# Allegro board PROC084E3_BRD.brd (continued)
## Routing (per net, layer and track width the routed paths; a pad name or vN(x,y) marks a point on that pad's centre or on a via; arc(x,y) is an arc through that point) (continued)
MCAN4_TX: length 94
  L03_SIG1 w0.102: v1(71.19,100.5) 67.51,100.5 49.1,118.91 48.78,118.91 43.67,124.02 43.67,155.88 39.39,160.16 J15.1
  BOTTOM w0.173: U29.54 70.69,100 v1(71.19,100.5) ; U15.1 29.46,160.92 J15.1
MCAN5_RX: length 98.3
  L03_SIG1 w0.102: v1(71.19,97) 71.19,97.58 70.74,98.04 70.74,98.69 71.09,99.04 71.38,99.04 71.65,99.31 71.65,100.69 71.38,100.96 67.75,100.96 49.52,119.18 49.52,120.09 45.23,124.38 45.23,156.54 37.92,163.84 J13.2
  BOTTOM w0.173: U29.47 70.69,96.5 v1(71.19,97) ; R126.1 29.08,162.7 J13.2
MCAN5_TX: length 100.5
  L03_SIG1 w0.102: J13.1 36.97,166.38 45.54,157.82 45.54,124.55 68.9,101.18 71.48,101.18 71.88,100.78 71.88,99.18 v1(71.19,98.5)
  BOTTOM w0.173: U29.50 70.69,98 v1(71.19,98.5) ; J13.1 29.59,167.02 U11.1
MCAN6_RX: length 105.6
  L03_SIG1 w0.102: J11.2 36.58,170.07 46.02,160.62 46.02,124.39 68.99,101.41 71.57,101.41 72.11,100.88 72.11,97.27 71.3,96.46 71,96.46 70.74,96.19 70.74,95.46 v1(71.19,95)
  BOTTOM w0.173: J11.2 28.96,168.8 R117.1 ; v1(71.19,95) 70.69,94.5 U29.43
MCAN6_TX: length 111.5
  L03_SIG1 w0.102: J11.1 39.96,172.61 46.33,166.24 46.33,124.4 69.09,101.64 71.8,101.64 72.42,101.03 72.42,97.22 v1(71.19,96)
  BOTTOM w0.173: U9.1 29.72,173.12 J11.1 ; U29.45 70.69,95.5 v1(71.19,96)
MCAN7_RX: length 118.4
  L03_SIG1 w0.102: J9.2 31.34,177.15 41.2,177.15 46.79,171.57 46.79,124.33 69.22,101.9 71.9,101.9 72.64,101.16 72.64,95.8 71.33,94.48 71.02,94.48 70.74,94.19 70.74,93.46 v1(71.19,93)
  BOTTOM w0.173: v1(71.19,93) 70.69,92.5 U29.39 ; R113.1 29.21,175.02 J9.2
MCAN7_TX: length 120
  L03_SIG1 w0.102: J9.1 31.34,177.46 41.33,177.46 47.09,171.69 47.09,124.35 69.31,102.13 72.03,102.13 72.87,101.28 72.87,95.68 v1(71.19,94)
  BOTTOM w0.173: U8.1 29.59,179.21 J9.1 ; U29.41 70.22,93.5 70.72,94 v1(71.19,94)
MCAN9_RX: length 117.1
  TOP w0.173: J1.55 v1(84.01,106.01)
  L03_SIG1 w0.102: J7.2 42.24,182.01 48.54,175.71 48.54,165.84 62.26,152.13 62.26,137.85 76.78,123.33 76.78,114.93 75.16,113.31 75.16,107.43 76.36,106.24 81.94,106.24 82.19,106.49 83.52,106.49 v1(84.01,106.01)
  BOTTOM w0.173: J7.2 29.46,181.24 R110.1
MCAN9_TX: length 124.8
  TOP w0.173: v1(82.86,106.01) 83.31,106.01 83.81,105.51 J1.53
  L03_SIG1 w0.102: v1(82.86,106.01) 76.27,106.01 74.87,107.4 74.87,113.34 76.55,115.02 76.55,123.24 62.03,137.76 62.03,152.03 48.23,165.83 48.23,175.58 43.33,180.48 29.57,180.48 28.93,181.12 28.93,183.25 J7.1
  BOTTOM w0.173: U7.1 29.46,185.31 J7.1
MCAN11_RX: length 123.5
  TOP w0.173: J1.60 v1(92.43,107.01)
  L03_SIG1 w0.102: v1(92.43,107.01) 88.61,110.83 81.09,110.83 80.36,111.57 80.36,112.78 77.02,116.13 77.02,123.79 64.59,136.21 64.59,158.13 49.43,173.29 49.43,177.92 37.87,189.47 31.34,189.47 J4.2
  BOTTOM w0.173: J4.2 29.21,187.34 R107.1
MCAN11_TX: length 128.8
  TOP w0.173: v1(93.58,107.01) 93.08,106.51 J1.58
  L03_SIG1 w0.102: J4.1 31.34,189.78 38,189.78 49.73,178.04 49.73,173.31 64.82,158.22 64.82,138.24 77.24,125.82 77.24,116.25 80.7,112.79 80.7,111.57 81.17,111.1 89.49,111.1 v1(93.58,107.01)
  BOTTOM w0.173: U6.1 29.72,191.4 J4.1
MCAN/PWM_SEL: length 76.7
  TOP w0.173: v1(81.35,90.36) 81.02,90.36 80.93,90.44 75.79,90.44 75.04,91.19 75.04,99.1 77.5,101.56 79.06,101.56 79.34,101.28 v1(79.34,101.26) ; J2.32 v1(93.58,50.63)
  BOTTOM w0.173: v1(81.35,90.36) 81.22,90.22 81.22,75.26 80.06,74.11 80.06,66.14 81.29,64.91 82.29,64.91 83.67,63.54 91.83,63.54 92.23,63.14 92.54,63.14 93.83,61.85 93.83,58.99 94.82,57.99 94.82,51.88 v1(93.58,50.63) ; v1(79.34,101.26) 79,101.26 78.14,102.13 R167.2
MCAN/PWM_SEL_R: length 2.4
  BOTTOM w0.173: R164.1 R167.1 76.78,101.59 76.77,101.59 U29.1
MCU_ADC1_AIN0: length 183
  L06_SIG2 w0.102: J24.51 26.19,23.2 26.19,39.18 26.78,39.77 26.78,94.15 31.47,98.84 31.47,108.81 32.41,109.75 32.41,112.98 34.58,115.15 34.58,121.61 34.29,121.89 34.29,122.69 34.82,123.22 34.82,134.18 37.03,136.39 47.54,136.39 47.56,136.41 47.59,136.41 51.32,140.14 68.24,140.14 69.75,141.65 69.75,144.13 J16.6
  BOTTOM w0.173: J16.6 71.05,147.34 72.34,148.63 77.6,148.63 80.88,151.91 U17.3
MCU_ADC1_AIN1: length 186.8
  L06_SIG2 w0.102: J24.53 31.91,17.08 25.96,23.03 25.96,39.28 26.55,39.87 26.55,95.69 31.24,100.39 31.24,122.2 34.01,124.96 34.01,133.98 36.65,136.62 47.44,136.62 51.26,140.44 66.59,140.44 67.41,141.26 67.41,144.33 J16.8
  BOTTOM w0.173: J16.8 68.51,147.08 70.93,149.49 74.35,149.49 78.16,153.31 U12.3
MCU_ADC1_AIN2: length 176.2
  L06_SIG2 w0.102: J16.10 64.72,144.18 64.72,141.44 64.13,140.85 51.29,140.85 47.29,136.85 36.55,136.85 33.59,133.89 33.59,125.35 31.01,122.77 31.01,100.48 26.32,95.79 26.32,40 25.73,39.41 25.73,22.93 29.91,18.75 J24.55
  BOTTOM w0.173: J16.10 65.97,147.75 68.48,150.26 72.97,150.26 74.63,151.91 U18.3
MCU_ADC1_AIN3: length 183.2
  L06_SIG2 w0.102: J24.57 27.91,20.37 25.5,22.77 25.5,39.62 26.08,40.21 26.08,95.87 30.78,100.58 30.78,123.41 32.76,125.38 32.76,136.32 34.03,137.59 38.23,137.59 38.73,137.09 47.03,137.09 51.18,141.24 52.94,141.24 52.94,141.24 61.47,141.24 62.15,141.92 62.15,144.15 J16.12
  BOTTOM w0.173: J16.12 63.43,149.15 65.46,151.17 70.97,151.17 71.76,151.96 U13.3
MCU_ADC1_AIN4: length 178.8
  TOP w0.173: v1(62.79,149.83) 62.34,149.38 R280.2
  L06_SIG2 w0.102: v1(62.79,149.83) 60.29,147.33 53.45,147.33 43.49,137.37 39.06,137.37 38.52,137.91 33.89,137.91 31.45,135.47 31.45,125.49 30.56,124.59 30.56,100.67 25.85,95.97 25.85,40.55 24.21,38.9 24.21,12.96 25.06,12.11 28.54,12.11 J24.56
  BOTTOM w0.173: v1(62.79,149.83) 62.79,151.04 63.66,151.91 67.67,151.91 67.92,152.17 U19.3
MCU_ADC1_AIN5: length 180.9
  TOP w0.173: R278.2 v1(59.07,149.65)
  L06_SIG2 w0.102: v1(59.07,149.65) 57.13,147.71 52.35,147.71 42.25,137.61 39.28,137.61 38.62,138.26 33.75,138.26 31.22,135.74 31.22,125.93 30.33,125.04 30.33,101.82 25.63,97.12 25.63,40.65 23.98,39 23.98,12.86 24.96,11.88 30.31,11.88 J24.54
  BOTTOM w0.173: U14.3 63.66,155.54 59.07,150.96 v1(59.07,149.65)
MCU_ADC1_AIN6: length 173.3
  TOP w0.173: R274.2 v1(55.81,149.65)
  L06_SIG2 w0.102: v1(55.81,149.65) 55.32,149.16 53.12,149.16 42.04,138.09 41.09,138.09 40.62,138.56 33.63,138.56 29.97,134.91 29.97,101.79 25.4,97.21 25.4,40.74 23.75,39.09 23.75,12.77 24.89,11.62 32.05,11.62 J24.52
  BOTTOM w0.173: U20.3 57.21,151.91 55.81,150.52 v1(55.81,149.65)
MCU_ADC1_AIN7: length 192.5
  L06_SIG2 w0.102: v1(74.56,139.67) 61.25,139.67 60.76,139.18 50.72,139.18 47.58,136.04 39.46,136.04 38.73,135.31 36.97,135.31 35.32,133.66 35.32,115.01 32.83,112.52 32.83,99.87 30.96,98 27.05,94.09 27.05,63.2 28.03,62.21 28.03,59.73 27.05,58.75 27.05,39.7 26.46,39.11 26.46,23.34 32.36,17.44 33.95,17.44 J24.49
  BOTTOM w0.173: v1(74.56,139.67) R148.1 77.02,140.45 77.95,141.38 77.95,148.26 79.95,150.27 85.23,150.27 87.05,152.09 U16.3
MCU_ADC_EXT_TRIGGER1: length 100.7
  TOP w0.173: J2.103 v1(84.01,73.63)
  L03_SIG1 w0.102: v1(84.01,73.63) 82.66,73.63 80.64,71.62 80.64,67.94 79.98,67.28 68.53,67.28 63.89,62.64 63.89,44.76 63.04,43.91 61.72,43.91 58.83,41.01 58.83,39.88 52.54,33.6 41.68,33.6 37.21,29.13 37.21,28.63 36.35,27.77 35.17,27.77 26.91,19.51 26.91,14.48 J24.58
MDIO0_MDC: length 149.9
  TOP w0.173: v1(58.35,58.45) 58.95,57.85 73.55,57.85 v1(74.92,59.22) ; J1.97 83.77,121.51 83.42,121.17 v1(80.32,121.17)
  L03_SIG1 w0.102: v1(58.35,58.45) 57.91,58.01 57.91,41.99 54.81,38.89 54.81,38.74 54.32,38.24 52.93,38.24 52.53,38.64 52.53,39.12 52.26,39.38 51.88,39.38 51.38,38.89 51.38,38.74 51.12,38.47 49.78,38.47 46.73,35.41 40.66,35.41 36,30.75 v1(36,29.06)
  BOTTOM w0.173: v1(36,29.06) 36.08,29.06 36.39,28.75 U40.20 ; U35.10 59,59.1 v1(58.35,58.45) ; v1(80.32,121.17) 80.32,115.12 78.67,113.47 78.67,110.42 81.15,107.93 81.17,107.93 81.34,107.76 81.34,106.2 80.36,105.23 80.36,98.54 79.74,97.91 79.74,75.6 79.03,74.89 79.03,67.82 78.49,67.28 78,67.28 76.62,65.9 71.03,65.9 69.21,64.08 69.21,60.32 70.31,59.22 U34.10 v1(74.92,59.22)
MDIO0_MDIO: length 146.4
  TOP w0.173: v1(80.57,122.02) 81.08,121.51 83.06,121.51 83.56,122.01 J1.99 ; v1(58.35,61.05) 59.52,62.22 v1(69.71,62.22)
  L03_SIG1 w0.102: v1(58.35,61.05) 57.51,60.2 57.51,52.72 56.87,52.08 56.87,50.38 57.51,49.75 57.51,41.94 55.43,39.87 54.65,39.87 53.9,39.12 53.9,38.97 53.4,38.47 53.02,38.47 52.76,38.74 52.76,39.21 52.35,39.61 51.79,39.61 51.68,39.51 49.12,39.51 45.25,35.64 40.45,35.64 36.17,31.36 35.2,31.36 v1(34.37,30.52)
  BOTTOM w0.173: v1(80.57,122.02) 80.85,121.74 80.85,115.17 79.05,113.37 79.05,110.52 81.3,108.28 81.31,108.28 81.68,107.9 81.68,107.89 81.73,107.84 81.73,105.62 80.74,104.64 80.74,98.09 80.08,97.44 80.08,75.41 79.37,74.7 79.37,67.68 78.63,66.94 78.15,66.94 76.77,65.56 76.74,65.56 76.6,65.41 71.35,65.41 69.71,63.77 v1(69.71,62.22) 69.71,61.78 70.31,61.17 U34.13 ; U40.19 35.89,28.46 34.37,29.99 v1(34.37,30.52) ; U35.13 v1(58.35,61.05)
MDIO_MDC_SEL0: length 24.6
  TOP w0.173: J2.34 92.57,51.13 v1(92.58,51.12)
  BOTTOM w0.173: v1(92.58,51.12) 93.42,51.12 94.48,52.18 94.48,57.84 93.37,58.95 93.37,61.8 93.36,61.82 93.36,61.82 92.79,62.39 92.79,62.39 92.56,62.61 84.7,62.61 84.17,63.13 R219.1
MDIO_MDC_SEL1: length 40.8
  TOP w0.173: v1(82.28,62.04) 82.03,61.79 80.54,61.79 76.88,65.45 68.76,65.45 v1(68,64.69) ; J2.36 92.77,51.63 v1(93.13,52)
  BOTTOM w0.173: v1(93.13,52) 93.75,52 94.1,52.34 94.1,56.26 93.01,57.35 93.01,61.68 92.65,62.04 v1(82.28,62.04) ; R298.1 v1(68,64.69)
MDIO_MDC_SEL_PRG0: length 2.8
  BOTTOM w0.173: U34.1 R215.1 82.07,63.12 R219.2
MDIO_MDC_SEL_PRG1: length 2.8
  BOTTOM w0.173: U35.1 R298.2 R299.1
MUX_MAIN_UART4_RTSN: length 100.6
  TOP w0.173: U42.3 70.97,42.44 v1(71.65,43.12)
  L06_SIG2 w0.102: v1(56.03,91.79) 56.03,90.82 55.27,90.06 55.27,79.97 53.9,78.6 53.9,73.45 52.25,71.8 52.25,68.06 54.13,66.18 v1(54.58,66.18)
  BOTTOM w0.173: v1(71.65,43.12) 70.61,43.12 66.55,47.18 66.55,49.26 59.51,56.31 58.62,56.31 54.58,60.34 v1(54.58,66.18) ; U22.3 46.34,118.72 45.54,117.92 45.54,109.42 46.56,108.4 54.87,108.4 56.57,106.7 56.57,92.9 56.03,92.37 v1(56.03,91.79)
MUX_MAIN_UART4_RXD: length 99.3
  TOP w0.173: U42.6 v1(72.92,43.07)
  L06_SIG2 w0.102: v1(55.65,66.18) 55.04,66.79 53.87,66.79 52.55,68.11 52.55,71.64 54.33,73.42 54.33,78.58 55.65,79.9 55.65,89.37 v1(56.92,90.64)
  BOTTOM w0.173: v1(72.92,43.07) 72.26,43.73 70.56,43.73 66.95,47.34 66.95,49.42 59.67,56.7 58.78,56.7 55.65,59.83 v1(55.65,66.18) ; U22.6 46.47,116.77 45.9,116.19 45.9,109.57 46.71,108.75 55.02,108.75 56.92,106.85 v1(56.92,90.64)
MUX_MAIN_UART4_TXD: length 101.6
  TOP w0.173: v1(72.92,44.21) 73.57,44.86 U42.10
  L06_SIG2 w0.102: v1(55.17,90.67) 54.89,90.39 54.89,80.02 53.57,78.7 53.57,73.65 51.92,72 51.92,67.07 53.26,65.72 56.39,65.72 v1(56.85,66.18)
  BOTTOM w0.173: U22.10 44.02,116.12 45.19,114.95 45.19,109.27 46.42,108.04 54.72,108.04 56.21,106.55 56.21,93.28 55.17,92.24 v1(55.17,90.67) ; v1(56.85,66.18) 56.44,65.78 56.44,59.63 58.95,57.11 59.84,57.11 67.36,49.6 67.36,47.51 70.66,44.21 v1(72.92,44.21)
MUX_MC/BP_SEL: length 211.4
  TOP w0.173: v1(97.71,109.84) 98.27,110.4 98.27,134.49 96.67,136.08 67.31,136.08 65.98,137.41 R273.2 ; U44.1 90.48,20.13 v1(91.44,21.1) ; J2.20 v1(90.22,47.63)
  L06_SIG2 w0.102: v1(91.44,21.1) 91.87,21.1 93.95,23.18 93.95,32.55 97.59,36.18 97.59,71.69 99.69,73.8 99.69,107.63 97.71,109.62 v1(97.71,109.84)
  BOTTOM w0.173: v1(91.44,21.1) 91.85,21.5 91.85,35.73 90.65,36.92 90.65,47.2 v1(90.22,47.63)
MUX_PRG1_UART0_RTSN: length 17.9
  TOP w0.173: v1(48.96,119.37) 49.52,118.81 50.6,118.81 51.13,119.34 v1(64.01,119.34)
  BOTTOM w0.173: U22.2 v1(48.96,119.37) ; U23.2 v1(64.01,119.34)
MUX_PRG1_UART0_RXD: length 20.5
  TOP w0.173: v1(49.98,116.77) 62.58,116.77 63.09,117.29 64.48,117.29 v1(65.02,116.74)
  BOTTOM w0.173: v1(65.02,116.74) 64.37,117.39 U23.5 ; U22.5 49.33,117.42 v1(49.98,116.77)
MUX_PRG1_UART0_TXD: length 20.5
  TOP w0.173: v1(54.98,117.39) 43.01,117.39 42.44,116.83 40.52,116.83 v1(39.94,117.42)
  BOTTOM w0.173: v1(39.94,117.42) 40.59,116.77 U22.11 ; v1(54.98,117.39) 55.63,116.74 U23.11
PERIPH_RSTZ: length 163.5
  TOP w0.173: v1(96.11,50.13) 93.07,50.13 92.57,49.63 J2.28
  L03_SIG1 w0.102: v1(96.11,50.13) 98.65,52.67 98.65,100.78 97.21,102.22 97.21,121.48 86.44,132.25 86.44,158.03 67.31,177.15 67.31,187.27 J5.10
  BOTTOM w0.173: v1(96.11,50.13) 93.07,50.13 92,49.06 TP28.1
PG_V2V5: length 13.2
  TOP w0.254: v1(62.64,100.55) 62.18,100.09 R7.2 52.22,100.17 v1(52.22,100.9)
  BOTTOM w0.254: U28.3 52.45,100.67 v1(52.22,100.9) ; v1(62.64,100.55) 62.26,100.55 61.96,100.25 U27.5
PRG0_MDC: length 47.5
  TOP w0.173: U5.16 v1(37.62,53.96)
  L03_SIG1 w0.102: v1(53.24,49.32) 52.61,48.68 39.5,48.68 37.85,50.34 37.85,53.74 v1(37.62,53.96)
  L06_SIG2 w0.102: v1(69.33,59.13) 64.28,59.13 56.96,51.81 56.96,50.63 56.34,50 53.93,50 v1(53.24,49.32)
  BOTTOM w0.173: U37.16 v1(53.24,49.32) ; v1(69.33,59.13) 69.88,58.57 U34.9
PRG0_MDIO: length 48.3
  TOP w0.173: v1(38.51,53.96) 38.51,53.99 38.51,53.99 38.51,54.04 38.12,54.43 U5.17
  L03_SIG1 w0.102: v1(54.13,49.32) 53.67,49.77 38.73,49.77 38.07,50.43 38.07,53.69 38.35,53.96 v1(38.51,53.96)
  L06_SIG2 w0.102: v1(54.13,49.32) 56.7,49.32 57.88,50.5 57.88,50.91 64.96,57.99 69.33,57.99 69.81,58.48 69.81,60.52 v1(69.82,60.52)
  BOTTOM w0.173: U37.17 53.74,48.86 54.13,49.24 54.13,49.29 54.13,49.3 v1(54.13,49.32) ; U34.12 v1(69.82,60.52)
PRG0_MDIO0_MDC: length 6.8
  L03_SIG1 w0.102: v1(75.49,60.3) 75.49,60.48 v1(77.27,62.27)
  BOTTOM w0.173: U34.11 75.06,59.87 v1(75.49,60.3) ; v1(77.27,62.27) 77.47,62.47 U34.2
PRG0_MDIO0_MDIO: length 8.6
  TOP w0.173: v1(80.52,60.61) 80.38,60.47 R287.1
  BOTTOM w0.173: U34.14 76.3,61.82 77.6,60.52 U34.5 80.43,60.52 v1(80.52,60.61)
PRG0_RGMII1_100MBPS: length 13.7
  TOP w0.173: J21.A13 6.78,50.43 4.97,48.62 4.97,44.27 7.13,42.11 R80.2 7.13,40.93 Q9.3
PRG0_RGMII1_1000MBPS: length 10
  TOP w0.173: J21.A14 14.24,43.16 R82.2 14.24,40.93 Q11.3
PRG0_RGMII1_ACT_LED: length 5.9
  TOP w0.173: J21.A11 10.41,55.9 Q7.3
PRG0_RGMII1_CLK_OUT: length 7.7
  TOP w0.173: v1(54.24,47.5) 51.44,50.31 v1(50.95,50.31)
  BOTTOM w0.173: U37.18 v1(54.24,47.5) ; TP16.1 v1(50.95,50.31)
PRG0_RGMII1_D0_N: length 41.6
  BOTTOM w0.102: J21.A2 13.82,49.27 13.82,48.33 14.15,47.99 14.15,46.69 15.87,44.98 25.25,44.98 27.75,42.47 50.22,42.47 50.34,42.59 U37.2
PRG0_RGMII1_D0_P: length 41.6
  BOTTOM w0.102: J21.A1 13.62,48.15 13.88,47.88 13.88,46.58 15.76,44.71 25.14,44.71 27.64,42.21 50.22,42.21 50.34,42.09 U37.1
PRG0_RGMII1_D1_N: length 38.1
  BOTTOM w0.102: U37.5 50.34,44.09 50.22,43.97 27.65,43.97 25.93,45.69 18.07,45.69 16.69,47.08 16.69,48.02 16.41,48.3 16.41,49.32 J21.A4
PRG0_RGMII1_D1_P: length 38.2
  BOTTOM w0.102: J21.A3 16.18,48.15 16.42,47.91 16.42,46.97 17.96,45.43 25.82,45.43 27.54,43.71 50.22,43.71 50.34,43.59 U37.4
PRG0_RGMII1_D2_N: length 35.6
  BOTTOM w0.102: U37.8 50.34,45.59 50.22,45.47 43.04,45.47 42.29,44.72 28.19,44.72 26.46,46.45 19.84,46.45 19.23,47.06 19.23,48.02 18.95,48.3 18.95,49.32 J21.A6
PRG0_RGMII1_D2_P: length 35.7
  BOTTOM w0.102: U37.7 50.34,45.09 50.22,45.21 43.16,45.21 42.4,44.45 28.08,44.45 26.35,46.18 19.73,46.18 18.96,46.95 18.96,47.91 18.72,48.15 J21.A5
PRG0_RGMII1_D3_N: length 32.8
  BOTTOM w0.102: U37.11 50.34,47.09 50.22,46.97 42.64,46.97 41.27,45.61 29.21,45.61 27.74,47.08 22,47.08 21.77,47.31 21.77,47.99 21.49,48.27 21.49,49.32 J21.A8
PRG0_RGMII1_D3_P: length 32.8
  BOTTOM w0.102: J21.A7 21.24,48.15 21.5,47.88 21.5,47.2 21.89,46.81 27.63,46.81 29.1,45.34 41.39,45.34 42.75,46.71 50.22,46.71 50.34,46.59 U37.10
PRG0_RGMII1_GPIO0_100: length 63.1
  TOP w0.173: Q9.1 v1(5.91,37.45) ; v1(55.5,38.93) R92.1
  L03_SIG1 w0.102: v1(5.91,37.45) 6.37,36.99 18.8,36.99 26.34,29.45 29.83,29.45 30.94,28.34 36.27,28.34 36.75,28.82 36.75,29.32 42.38,34.96 51.53,34.96 v1(55.5,38.93)
  BOTTOM w0.173: R92.1 v1(55.5,38.93) 56.24,39.67 U37.39
PRG0_RGMII1_GPIO1: length 4.7
  TOP w0.173: v1(54.36,38.93) R91.1
  BOTTOM w0.173: R91.1 v1(54.36,38.93) 54.74,38.93 55.9,40.09 55.9,40.69 55.74,40.84 U37.40
PRG0_RGMII1_LED0: length 4.4
  TOP w0.173: v1(50.93,38.93) R88.1
  BOTTOM w0.173: R88.1 v1(50.93,38.93) 52.24,40.24 U37.47
PRG0_RGMII1_LED1_1000: length 54.1
  TOP w0.173: v1(52.07,38.93) R89.1 ; Q11.1 v1(13.02,37.45)
  L03_SIG1 w0.102: v1(52.07,38.93) 52.07,38.29 48.96,35.18 40.76,35.18 36.53,30.95 36.53,28.94 36.15,28.56 31.04,28.56 29.86,29.74 26.89,29.74 18.57,38.06 13.64,38.06 v1(13.02,37.45)
  BOTTOM w0.173: U37.46 52.74,39.6 v1(52.07,38.93) R89.1
PRG0_RGMII1_LED2_ACT: length 57.4
  TOP w0.173: Q7.1 v1(11.36,61.21) ; v1(53.21,38.93) R90.1
  L03_SIG1 w0.102: v1(11.36,61.21) 14.29,58.28 20.74,58.28 40.45,38.58 47.43,38.58 49.28,40.43 51.86,40.43 53.21,39.08 v1(53.21,38.93)
  BOTTOM w0.173: R90.1 v1(53.21,38.93) 53.21,41.31 U37.45
PRG0_RGMII1_RBIAS: length 2.3
  TOP w0.173: v1(49.91,47.59) 50.43,47.59 50.52,47.49 R77.2
  BOTTOM w0.173: U37.12 v1(49.91,47.59)
PRG0_RGMII1_RD0: length 107.2
  TOP w0.173: v1(82.54,113.59) 82.56,113.59 82.58,113.56 82.83,113.56 83.77,114.51 J1.69
  L06_SIG2 w0.102: v1(82.54,113.59) 82.6,113.65 82.6,114.52 82.14,114.97 82.14,116.58 82.54,116.97 88.53,116.97 88.93,116.56 88.93,89.14 87.35,87.56 87.35,73 85.97,71.61 85.97,70.06 84.48,68.58 83.78,68.58 83.56,68.8 81.41,68.8 79.75,67.15 77.77,67.15 72.3,61.67 72.3,58.67 68.65,55.02 65.27,55.02 61.37,51.12 61.37,45.13 63.73,42.76 v1(63.73,41.57)
  BOTTOM w0.173: R241.1 64.27,41.69 64.15,41.57 v1(63.73,41.57)
PRG0_RGMII1_RD0_R: length 7.1
  BOTTOM w0.173: R241.2 62.89,42.72 61.27,42.72 R78.1 60.59,42.1 R79.2 60.56,43.43 58.65,43.43 58.49,43.59 U37.33
PRG0_RGMII1_RD1: length 107.7
  TOP w0.173: J1.77 84.26,116.51 84.01,116.26 v1(83.88,116.26)
  L06_SIG2 w0.102: v1(83.88,116.26) 84.13,116.51 86.54,116.51 87.43,115.62 87.43,105.76 88.08,105.1 88.08,100.83 87.5,100.26 87.5,92.43 88.47,91.46 88.47,89.33 84.79,85.64 84.79,77.38 85.75,76.42 85.75,72.13 85.22,71.59 83.32,71.59 80.24,68.52 78.09,68.52 71.75,62.17 71.75,58.85 68.4,55.5 65.07,55.5 60.88,51.32 60.88,43.8 59.11,42.02 59.11,39.81 59.95,38.96 61.48,38.96 62.25,39.74 64.17,39.74 64.78,40.35 v1(64.78,41.24)
  BOTTOM w0.173: R242.1 64.55,41.24 v1(64.78,41.24)
PRG0_RGMII1_RD1_R: length 6.4
  BOTTOM w0.173: R242.2 62.62,41.33 60.27,41.33 59.91,41.69 59.91,42.28 59.09,43.09 U37.34
PRG0_RGMII1_RD2: length 107.9
  TOP w0.173: J1.75 v1(86.28,116.01)
  L06_SIG2 w0.102: v1(62.92,38.57) 62.54,38.57 62.5,38.62 62.18,38.62 62.18,38.62 62.02,38.62 61.65,38.25 59.61,38.25 59.12,37.76 57.88,37.76 57.28,38.36 57.28,40.69 60.66,44.07 60.66,51.41 64.97,55.73 68.3,55.73 71.51,58.94 71.51,62.26 78,68.75 80.15,68.75 81.99,70.59 81.99,81.89 82.09,81.99 82.37,81.99 82.47,81.89 82.47,80.43 82.58,80.33 82.85,80.33 82.96,80.43 82.96,84.13 88.25,89.42 88.25,91.37 87.27,92.34 87.27,100.35 87.85,100.93 87.85,104.98 87.57,105.26 87.2,105.63 87.2,115.1 v1(86.28,116.01)
  BOTTOM w0.173: R243.1 64.1,39.27 63.41,38.57 v1(62.92,38.57)
PRG0_RGMII1_RD2_R: length 8.2
  BOTTOM w0.173: R243.2 62.82,39.94 61.28,39.94 R85.1 R84.2 59.89,40.7 59.48,41.1 59.48,41.98 58.87,42.59 U37.35
PRG0_RGMII1_RD3: length 107.3
  TOP w0.173: v1(83.14,116.24) 83.17,116.24 83.68,116.75 83.99,116.75 84.25,117.01 J1.79
  L06_SIG2 w0.102: v1(62.31,38.16) 62.15,38.16 61.86,37.87 59.6,37.87 58.36,36.62 57.49,36.62 56.9,37.21 56.9,40.75 60.43,44.28 60.43,51.51 64.88,55.96 68.21,55.96 71.27,59.02 71.27,62.84 78.24,69.81 78.94,69.81 81.46,72.33 81.46,82.96 81.99,83.49 88.02,89.52 88.02,91.27 87.02,92.27 87.02,100.42 87.62,101.02 87.62,104.88 86.97,105.53 86.97,114.53 85.89,115.61 83.88,115.61 83.25,116.24 v1(83.14,116.24)
  BOTTOM w0.173: R244.1 v1(62.31,38.16)
PRG0_RGMII1_RD3_R: length 5.6
  BOTTOM w0.173: U37.36 58.56,42.09 58.91,41.74 58.91,39.57 60.32,38.16 R244.2
PRG0_RGMII1_REF_CLK: length 34.4
  L06_SIG2 w0.102: v1(54.23,52.12) 54.62,52.12 59.72,57.22 61.19,57.22 74.63,70.65 v1(78.53,70.65)
  BOTTOM w0.173: v1(54.23,52.12) 54.23,50.61 R232.1 ; R196.2 v1(78.53,70.65)
PRG0_RGMII1_REF_CLK_R: length 1.9
  BOTTOM w0.173: R196.1 76.83,70.62 U31.2
PRG0_RGMII1_RESET#: length 20.2
  TOP w0.173: v1(47.74,34.5) 54.88,34.5 57.89,37.51 57.89,38.93 57.39,39.42 54.06,39.42 v1(53.74,39.74)
  BOTTOM w0.173: U37.43 54.24,40.24 v1(53.74,39.74) ; U38.4 v1(47.74,34.5)
PRG0_RGMII1_RX_CTL: length 107.2
  TOP w0.173: J1.71 v1(84.01,115.01)
  L06_SIG2 w0.102: v1(84.01,115.01) 85.03,115.01 85.34,114.7 85.34,109.64 86.74,108.24 86.74,105.44 87.39,104.79 87.39,101.12 86.79,100.52 86.79,92.18 87.79,91.18 87.79,89.61 81.9,83.72 81.23,83.05 81.23,72.49 78.78,70.04 74.39,70.04 70.42,66.07 70.42,58.49 68.11,56.19 64.78,56.19 60.2,51.6 60.2,44.48 56.51,40.8 56.51,39.12 55.13,37.73 55.13,35.06 55.66,34.53 56.3,34.53 56.81,35.04 v1(56.81,35.74)
  BOTTOM w0.173: v1(56.81,35.74) 57.22,35.33 58.46,35.33 58.65,35.51 R250.1
PRG0_RGMII1_RX_CTL_R: length 7.7
  BOTTOM w0.173: R250.2 57.3,36.34 57.3,37.56 R251.2 R93.1 58.04,38.9 56.74,40.21 U37.38
PRG0_RGMII1_RXC: length 107.5
  TOP w0.173: v1(82.97,114.8) 82.97,115.12 83.36,115.51 J1.73
  L06_SIG2 w0.102: v1(64.57,43.59) 64.57,41.76 63.87,41.06 63.36,41.06 62.67,41.75 62.67,42.12 61.11,43.68 61.11,51.22 65.16,55.28 68.59,55.28 72.01,58.7 72.01,62.11 77.4,67.5 79.56,67.5 82.73,70.68 84.71,70.68 86.06,72.02 86.06,76.79 85.09,77.75 85.09,85.62 88.7,89.23 88.7,91.56 88.57,91.69 87.73,92.53 87.73,100.17 88.31,100.74 88.31,105.21 87.66,105.86 87.66,115.72 86.64,116.74 82.97,116.74 82.41,116.17 82.41,115.36 v1(82.97,114.8)
  BOTTOM w0.173: R240.1 64.27,43.89 v1(64.57,43.59)
PRG0_RGMII1_RXC_R: length 5.1
  BOTTOM w0.173: R240.2 62.73,44 59.24,44 59.11,43.87 58.7,43.87 58.48,44.09 U37.32
PRG0_RGMII1_TD0: length 101
  TOP w0.173: J1.72 v1(92.43,115.01)
  L06_SIG2 w0.102: v1(92.43,115.01) 92.43,114.86 92.78,114.52 93.74,114.52 94.06,114.21 94.06,111.87 90.66,108.47 90.66,88.68 89.41,87.43 89.41,75.83 88.64,75.07 88.64,71.59 87.47,70.42 87.47,67.95 85.49,65.97 81.03,65.97 78.02,62.96 75.38,62.96 73.52,61.1 73.52,55.2 65.09,46.76 64.92,46.76 64.73,46.95 64.73,47.09 68.43,50.79 68.43,51.03 68.33,51.13 68.09,51.13 64.98,48.02 v1(62.36,48.02)
  BOTTOM w0.173: R235.1 v1(62.36,48.02)
PRG0_RGMII1_TD0_R: length 3.7
  BOTTOM w0.173: R235.2 60.02,47.44 60.02,46.95 59.16,46.09 U37.28
PRG0_RGMII1_TD1: length 100.9
  TOP w0.173: J1.70 93.08,114.51 v1(93.58,114.01)
  L06_SIG2 w0.102: v1(62.36,49.16) 64.57,49.16 72.23,56.82 72.47,56.82 72.57,56.72 72.57,56.48 68.1,52.02 68.1,51.88 68.43,51.56 68.57,51.56 73.29,56.28 73.29,61.2 75.33,63.24 77.94,63.24 80.9,66.19 85.39,66.19 87.16,67.96 87.16,70.45 88.35,71.64 88.35,75.34 89.15,76.15 89.15,87.49 89.18,87.52 89.18,87.52 89.69,88.03 89.69,107.91 93.58,111.8 v1(93.58,114.01)
  BOTTOM w0.173: R234.1 v1(62.36,49.16)
PRG0_RGMII1_TD1_R: length 4.3
  BOTTOM w0.173: R234.2 59.67,48.24 59.67,47.14 59.12,46.59 U37.27
PRG0_RGMII1_TD2: length 101
  TOP w0.173: J1.78 93.08,116.51 v1(93.58,116.01)
  L06_SIG2 w0.102: v1(93.58,116.01) 93.58,115.58 93.47,115.48 92.2,115.48 91.77,115.06 91.77,113.91 93.33,112.35 93.33,111.94 89.41,108.02 89.41,88.31 88.93,87.82 88.93,80.1 88.82,80 88.05,80 87.95,79.9 87.95,79.62 88.05,79.52 88.82,79.52 88.93,79.41 88.93,79.13 88.82,79.03 88.05,79.03 87.95,78.93 87.95,78.65 88.05,78.55 88.82,78.55 88.93,78.45 88.93,78.17 88.82,78.07 88.05,78.07 87.95,77.97 87.95,77.69 88.05,77.58 88.82,77.58 88.93,77.48 88.93,76.35 88.77,76.19 88.06,76.19 87.96,76.09 87.96,71.83 86.81,70.69 86.81,68.13 86.48,67.8 86.1,67.8 85.84,68.06 84.59,68.06 84.42,67.9 84.42,67.43 84.59,67.27 85.71,67.27 85.82,67.16 85.82,66.94 85.3,66.42 82.48,66.42 82.38,66.53 82.38,67.79 82.2,67.98 81.69,67.98 77.18,63.46 74.76,63.46 73.06,61.77 73.06,58.07 65.3,50.31 v1(62.36,50.31)
  BOTTOM w0.173: R233.1 v1(62.36,50.31)
PRG0_RGMII1_TD2_R: length 4.9
  BOTTOM w0.173: U37.26 58.94,47.09 59.33,47.48 59.33,49.04 R233.2
PRG0_RGMII1_TD3: length 100.9
  TOP w0.173: J1.76 v1(92.43,116.01)
  L06_SIG2 w0.102: v1(62.36,51.45) 65.96,51.45 72.84,58.32 72.84,61.88 74.64,63.69 77.07,63.69 81.93,68.55 83.49,68.55 83.68,68.35 84.2,68.35 84.26,68.29 85.68,68.29 86.27,68.88 86.27,71.59 87.71,73.03 87.71,87.41 87.82,87.52 88.06,87.52 88.2,87.38 88.2,80.61 88.34,80.47 88.54,80.47 88.67,80.6 88.67,88.08 89.18,88.58 89.18,108.14 92.94,111.9 92.94,112.38 91.55,113.78 91.55,115.82 91.74,116.01 v1(92.43,116.01)
  BOTTOM w0.173: R229.1 v1(62.36,51.45)
PRG0_RGMII1_TD3_R: length 5.3
  BOTTOM w0.173: U37.25 58.57,47.59 58.98,48 58.98,49.84 R229.2
PRG0_RGMII1_TX_CTL: length 101.3
  TOP w0.173: v1(93.58,115.01) 93.08,115.51 J1.74
  L06_SIG2 w0.102: v1(59.77,37.24) 61.02,37.24 61.09,37.17 62.18,37.17 65.24,40.23 65.24,41.43 65.07,41.6 65.07,45.71 64.96,45.82 64.96,46.12 74.04,55.21 74.04,61.28 75.49,62.73 78.35,62.73 81.36,65.74 85.58,65.74 88.69,68.85 88.69,71.32 88.87,71.5 88.87,74.91 89.64,75.68 89.64,87.33 90.88,88.58 90.88,108.38 94.28,111.78 94.28,114.3 v1(93.58,115.01)
  BOTTOM w0.173: R249.1 v1(59.77,37.24)
PRG0_RGMII1_TX_CTL_R: length 3.9
  BOTTOM w0.173: U37.37 57.24,40.5 59.19,38.56 R249.2
PRG0_RGMII1_TXC: length 101
  TOP w0.173: J1.80 v1(92.43,117.01)
  L06_SIG2 w0.102: v1(92.43,117.01) 93.76,117.01 94.54,116.23 94.54,111.71 91.11,108.28 91.11,88.49 89.92,87.29 89.92,76.53 90.65,75.79 90.65,68.8 87.36,65.51 82.06,65.51 77.39,60.84 75.23,60.84 74.35,59.95 74.35,48.49 71.59,45.73 69.99,45.73 68.35,44.09 66.35,44.09 65.48,44.96 v1(65.48,45.94)
  BOTTOM w0.173: v1(65.48,45.94) 64.54,46.88 R236.1
PRG0_RGMII1_TXC_R: length 3.1
  BOTTOM w0.173: R236.2 59.38,45.66 58.06,45.66 U37.29
PRG0_RGMII1_XIN: length 2.3
  BOTTOM w0.173: R232.2 52.74,50.11 U37.15
PRG0_RGMII1_XOUT: length 2.2
  BOTTOM w0.173: R231.2 52.24,50.15 U37.14
PRG0_RGMII2_100MBPS: length 17.3
  TOP w0.132: 8.46,49.41 9.88,49.41 10.85,50.39 J21.B13
  TOP w0.173: 8.46,49.41 6.78,49.41 5.51,48.15 5.51,44.82 7.21,43.12 9.8,43.12 10.14,42.78 R81.2 10.41,41.78 Q10.3
PRG0_RGMII2_1000MBPS: length 11.2
  TOP w0.173: J21.B14 15.67,43.58 16.89,43.58 17.25,43.21 R83.2 17.25,40.93 Q12.3
PRG0_RGMII2_ACT_LED: length 6.6
  TOP w0.173: Q8.3 13.97,59.65 11.58,57.27 11.58,55.22 J21.B11
PRG0_RGMII2_CLK_OUT: length 7.8
  TOP w0.173: U5.18 v1(38.62,55.78)
  BOTTOM w0.173: v1(38.62,55.78) 35.82,52.97 TP15.1
PRG0_RGMII2_D0_N: length 26.1
  TOP w0.102: U5.2 34.72,60.69 34.6,60.81 30.82,60.81 29.59,59.58 26.91,59.58 24.98,57.65 15.47,57.65 14.15,56.33 14.15,54.88 13.87,54.6 13.87,53.58 J21.B2
PRG0_RGMII2_D0_P: length 26.2
  TOP w0.102: J21.B1 13.64,54.75 13.88,54.99 13.88,56.44 15.36,57.91 24.87,57.91 26.8,59.84 29.48,59.84 30.71,61.07 34.6,61.07 34.72,61.19 U5.1
PRG0_RGMII2_D1_N: length 22.8
  TOP w0.102: J21.B4 16.41,53.58 16.41,54.6 16.69,54.88 16.69,56.07 17.69,57.08 25.61,57.08 27.23,58.69 33.4,58.69 34.02,59.31 34.6,59.31 34.72,59.19 U5.5
PRG0_RGMII2_D1_P: length 22.9
  TOP w0.102: J21.B3 16.18,54.75 16.42,54.99 16.42,56.19 17.58,57.34 25.5,57.34 27.12,58.96 33.29,58.96 33.91,59.57 34.6,59.57 34.72,59.69 U5.4
PRG0_RGMII2_D2_N: length 19.4
  TOP w0.102: J21.B6 18.95,53.58 18.95,54.6 19.23,54.88 19.23,55.69 19.99,56.46 26.41,56.46 27.76,57.81 34.6,57.81 34.72,57.69 U5.8
PRG0_RGMII2_D2_P: length 19.5
  TOP w0.102: U5.7 34.72,58.19 34.6,58.07 27.65,58.07 26.3,56.72 19.88,56.72 18.96,55.8 18.96,54.99 18.72,54.75 J21.B5
PRG0_RGMII2_D3_N: length 16.2
  TOP w0.102: U5.11 34.72,56.19 34.6,56.31 27.66,56.31 27.22,55.87 22.07,55.87 21.77,55.57 21.77,54.88 21.49,54.6 21.49,53.58 J21.B8
PRG0_RGMII2_D3_P: length 16.3
  TOP w0.102: U5.10 34.72,56.69 34.6,56.58 27.55,56.58 27.11,56.13 21.96,56.13 21.5,55.68 21.5,54.99 21.26,54.75 J21.B7
PRG0_RGMII2_GPIO0_100: length 67.7
  TOP w0.173: v1(29.36,33.21) 25.07,33.21 22.35,35.93 16.56,35.93 15.57,36.92 9.64,36.92 9.46,37.09 Q10.1 ; R56.2 v1(39.88,64.35) 40.62,63.61 U5.39
  L06_SIG2 w0.102: v1(39.88,64.35) 40.34,63.9 40.34,62.4 39.52,61.58 34.21,61.58 33.71,61.08 33.71,49.16 34.32,48.55 34.32,35.91 32.2,33.8 29.95,33.8 v1(29.36,33.21)
  BOTTOM w0.173: v1(39.88,64.35) R56.2
PRG0_RGMII2_GPIO1: length 4.7
  TOP w0.173: R55.2 v1(38.73,64.35) 39.12,64.35 40.28,63.19 40.28,62.61 40.12,62.45 U5.40
  BOTTOM w0.173: v1(38.73,64.35) R55.2
PRG0_RGMII2_LED0: length 4.4
  TOP w0.173: U5.47 36.62,63.04 v1(35.31,64.35) R52.2
  BOTTOM w0.173: v1(35.31,64.35) R52.2
PRG0_RGMII2_LED1_1000: length 54.6
  TOP w0.173: U5.46 37.12,63.68 v1(36.45,64.35) R53.2 ; v1(29.36,34.23) 25.73,34.23 23.22,36.74 17.07,36.74 16.58,37.24 Q12.1
  L06_SIG2 w0.102: v1(36.45,64.35) 36.45,64.15 33.45,61.15 33.45,49.09 34.09,48.46 34.09,36.01 32.31,34.23 v1(29.36,34.23)
  BOTTOM w0.173: v1(36.45,64.35) R53.2
PRG0_RGMII2_LED2_ACT: length 28.8
  TOP w0.173: Q8.1 v1(14.92,61.21) ; U5.45 37.62,62.5 37.47,62.65 37.47,64.23 v1(37.59,64.35) R54.2
  L03_SIG1 w0.102: v1(14.92,61.21) 15.2,61.49 33.94,61.49 35.13,62.68 35.92,62.68 v1(37.59,64.35)
  BOTTOM w0.173: v1(37.59,64.35) R54.2
PRG0_RGMII2_RBIAS: length 2.3
  TOP w0.173: U5.12 v1(34.29,55.69)
  BOTTOM w0.173: v1(34.29,55.69) 34.81,55.69 34.9,55.79 R227.2
PRG0_RGMII2_RD0: length 65
  TOP w0.173: v1(48.63,61.23) 48.38,60.98 R67.1 ; J1.13 83.36,95.51 v1(82.86,95.01)
  L03_SIG1 w0.102: v1(82.86,95.01) 81.81,93.95 81.81,89.6 75.33,83.12 64.23,83.12 60.59,79.48 60.4,79.48 56.43,79.48 54.56,77.61 54.56,76.6 45.65,67.69 45.65,63.95 46.05,63.55 46.05,63.31 46.08,63.29 46.08,61.12 46.22,60.97 46.81,60.97 47.33,60.45 48.03,60.45 48.63,61.05 v1(48.63,61.23)
PRG0_RGMII2_RD0_R: length 6.8
  TOP w0.173: R67.2 46.91,61 46.34,61.57 45.56,61.57 R223.2 R224.1 44.96,60.96 44.96,60.9 43.81,59.76 42.44,59.76 U5.33
PRG0_RGMII2_RD1: length 65.2
  TOP w0.173: v1(49.23,63.3) 48.33,62.4 R64.1 ; J1.15 v1(84.01,96.01)
  L03_SIG1 w0.102: v1(49.23,63.3) 49.69,63.76 49.69,67.21 57.23,74.74 59.33,74.74 64.06,79.47 73.27,79.47 85.53,91.72 88.89,91.72 89.21,92.05 89.21,95.21 88.41,96.01 v1(84.01,96.01)
PRG0_RGMII2_RD1_R: length 7.2
  TOP w0.173: R64.2 47.35,62.51 47.12,62.74 44.59,62.74 44.26,62.4 44.26,61.11 43.34,60.19 U5.34
PRG0_RGMII2_RD2: length 65
  TOP w0.173: v1(49.05,64.42) 48.74,64.11 48.74,63.91 48.31,63.48 R61.1 ; v1(82.86,96.01) 83.36,96.51 J1.17
  L03_SIG1 w0.102: v1(82.86,96.01) 82.95,96.09 83.27,96.09 83.81,95.55 87.31,95.55 87.71,95.15 87.71,92.28 87.52,92.09 85.56,92.09 73.16,79.69 63.96,79.69 59.24,74.97 55.91,74.97 48.44,67.5 48.44,64.73 48.75,64.42 v1(49.05,64.42)
PRG0_RGMII2_RD2_R: length 9.4
  TOP w0.173: R61.2 47.33,63.97 46.99,64.31 45.49,64.31 R218.1 44.9,63.73 44.91,63.72 R222.2 44.09,63.55 43.91,63.37 43.91,61.73 42.87,60.69 U5.35
PRG0_RGMII2_RD3: length 65
  TOP w0.173: v1(47.16,65.37) 46.49,66.04 R60.1 ; v1(82.86,94.01) 83.36,94.51 J1.9
  L03_SIG1 w0.102: v1(82.86,94.01) 82.12,93.26 82.12,89.59 75.37,82.84 71.37,82.84 71.26,82.74 71.26,82.27 71.16,82.17 70.88,82.17 70.78,82.27 70.78,82.74 70.68,82.84 70.4,82.84 70.3,82.74 70.3,82.27 70.2,82.17 69.92,82.17 69.82,82.27 69.82,82.74 69.71,82.84 69.43,82.84 69.33,82.74 69.33,82.27 69.23,82.17 68.95,82.17 68.85,82.27 68.85,82.74 68.75,82.84 65.94,82.84 65.84,82.74 65.84,82.46 65.94,82.36 67.78,82.36 67.88,82.27 67.88,81.99 67.77,81.88 63.31,81.88 60.68,79.25 56.52,79.25 54.89,77.62 54.89,75.22 51.64,71.97 50.26,71.97 47.16,68.87 v1(47.16,65.37)
PRG0_RGMII2_RD3_R: length 6.3
  TOP w0.173: R60.2 44.5,66.04 44.32,65.87 44.32,64.67 43.51,63.86 43.51,62.02 42.69,61.19 U5.36
PRG0_RGMII2_REF_CLK: length 52.4
  TOP w0.173: R73.1 38.61,52.67 v1(38.61,51.16)
  L03_SIG1 w0.102: v1(38.61,51.16) 38.95,51.16 39.85,50.26 48.87,50.26 55.75,57.14 55.75,60.23 63.15,67.63 65.41,67.63 65.41,67.63 65.79,67.63 67.69,67.63 69.42,69.36 v1(78.53,69.36)
  BOTTOM w0.173: R198.2 v1(78.53,69.36)
PRG0_RGMII2_REF_CLK_R: length 1.9
  BOTTOM w0.173: U31.3 76.86,69.35 R198.1
PRG0_RGMII2_RESET#: length 13.5
  TOP w0.173: U5.43 38.62,62.52 38.55,62.6 38.55,63.12 v1(38.12,63.54) ; U4.4 v1(28.31,65.48)
  BOTTOM w0.173: v1(38.12,63.54) 34.72,63.54 32.78,65.48 v1(28.31,65.48)
PRG0_RGMII2_RX_CTL: length 65.3
  TOP w0.173: v1(42.16,67.58) 41.53,68.21 41.13,68.21 R58.1 ; J1.11 v1(84.01,95.01)
  L03_SIG1 w0.102: v1(42.16,67.58) 41.1,68.64 41.1,75.12 45.95,79.97 53.88,79.97 54.15,79.71 60.49,79.71 64.24,83.45 75.34,83.45 81.31,89.42 81.31,89.75 80.89,90.17 80.89,90.54 81.31,90.96 81.31,94.15 82.63,95.47 83.55,95.47 v1(84.01,95.01)
PRG0_RGMII2_RX_CTL_R: length 7.8
  TOP w0.173: U5.38 41.12,63.64 42.47,65 R209.1 41.04,65.04 R57.2 41.13,65.06 41.68,65.61 41.68,66.58 R58.2
PRG0_RGMII2_RXC: length 65
  TOP w0.173: v1(49.25,62.1) 49.25,60.77 48.03,59.55 46.24,59.55 R68.1 ; J1.7 v1(84.01,94.01)
  L03_SIG1 w0.102: v1(49.25,62.1) 48.27,62.1 47.37,62.99 47.37,64.91 48.18,65.72 48.18,67.6 59.44,78.86 61.11,78.86 63.02,80.76 69.23,80.76 69.33,80.86 69.33,81.14 69.23,81.24 68.2,81.24 68.1,81.35 68.1,81.63 68.2,81.73 74.87,81.73 83.44,90.29 83.44,93.44 v1(84.01,94.01)
PRG0_RGMII2_RXC_R: length 2.9
  TOP w0.173: R68.2 44.55,59.41 43.08,59.41 42.86,59.19 U5.32
PRG0_RGMII2_TD0: length 102.6
  TOP w0.173: J1.85 83.36,118.51 v1(82.86,118.01) ; v1(47.98,54.12) 46.84,55.26 R70.1
  L06_SIG2 w0.102: v1(47.98,54.12) 47.98,53.52 48.08,53.42 48.87,53.42 49.35,53.9 49.35,58.39 51.16,60.2 62.83,60.2 75.21,72.58 78.56,72.58 80.26,74.28 80.26,81.89 80.26,86.25 84.81,90.8 84.81,94.68 84.91,94.78 85.19,94.78 85.29,94.68 85.29,92.9 85.39,92.8 85.67,92.8 85.78,92.9 85.78,107.63 81.18,112.23 81.18,117.15 82.04,118.01 v1(82.86,118.01)
PRG0_RGMII2_TD0_R: length 3.7
  TOP w0.173: R70.2 44.4,55.84 44.4,56.33 43.53,57.19 U5.28
PRG0_RGMII2_TD1: length 102
  TOP w0.173: R71.1 v1(46.74,54.12) ; J1.83 v1(84.01,118.01)
  L06_SIG2 w0.102: v1(84.01,118.01) 83.51,118.51 82.21,118.51 80.95,117.25 80.95,112.08 85.55,107.48 85.55,96.26 85.45,96.15 85.12,96.15 85.01,96.26 85.01,98.11 84.89,98.24 84.63,98.24 84.53,98.14 84.53,90.84 80.04,86.34 80.04,81.8 80.04,74.42 78.53,72.91 75.18,72.91 62.72,60.46 51.09,60.46 49.12,58.49 49.12,57.15 47.4,55.43 47.4,53.55 47.3,53.45 46.66,53.45 46.47,53.64 46.47,53.85 v1(46.74,54.12)
PRG0_RGMII2_TD1_R: length 4.3
  TOP w0.173: U5.27 43.5,56.69 44.05,56.14 44.05,55.04 R71.2
PRG0_RGMII2_TD2: length 102.7
  TOP w0.173: R72.1 v1(46.74,52.97) ; v1(82.86,119.01) 83.36,119.51 J1.89
  L06_SIG2 w0.102: v1(82.86,119.01) 82.39,119.01 80.72,117.34 80.72,111.88 85.32,107.28 85.32,99.43 82.35,96.46 82.35,93.84 82.25,93.74 81.97,93.74 81.86,93.84 81.86,94.58 81.76,94.68 81.48,94.68 81.38,94.58 81.38,90.97 81.81,90.54 81.81,90.17 81.38,89.74 81.38,88.01 79.81,86.44 79.81,81.7 79.81,74.58 78.57,73.34 75.22,73.34 63.07,61.19 59.55,61.19 59.24,61.5 54.53,61.5 53.73,60.71 51.02,60.71 48.9,58.58 48.9,57.25 47.29,55.64 46.34,55.64 46.12,55.42 46.12,52.64 46.22,52.53 46.95,52.53 47.05,52.64 47.05,52.87 46.95,52.97 v1(46.74,52.97)
PRG0_RGMII2_TD2_R: length 4.9
  TOP w0.173: R72.2 43.71,54.24 43.71,55.81 43.32,56.19 U5.26
PRG0_RGMII2_TD3: length 102.1
  TOP w0.173: J1.93 83.36,120.51 v1(82.86,120.01) ; R76.1 v1(46.74,51.83)
  L06_SIG2 w0.102: v1(46.74,51.83) 46.52,51.61 46.05,51.61 45.89,51.77 45.89,55.73 46.03,55.87 47.19,55.87 48.67,57.34 48.67,58.77 50.86,60.95 52.91,60.95 53.69,61.73 59.02,61.73 59.47,62.18 63.69,62.18 75.14,73.62 78.49,73.62 79.58,74.71 79.58,81.61 79.58,86.53 81.15,88.11 81.15,89.91 80.89,90.17 80.89,90.54 81.15,90.8 81.15,95.65 85.09,99.58 85.09,107.13 80.49,111.72 80.49,119.07 81.43,120.01 v1(82.86,120.01)
PRG0_RGMII2_TD3_R: length 5.1
  TOP w0.173: R76.2 43.36,53.44 43.36,54.98 42.65,55.69 U5.25
PRG0_RGMII2_TX_CTL: length 102.4
  TOP w0.173: J1.91 v1(84.01,120.01) ; R59.1 43.64,66.51 43.92,66.79 46.65,66.79 47.88,65.57 v1(47.88,64.4)
  L06_SIG2 w0.102: v1(84.01,120.01) 84.01,120.04 82.18,121.86 82.18,122.18 81.86,122.5 80.37,122.5 79.82,121.96 79.82,120.67 80.04,120.45 80.04,111.4 84.63,106.8 84.63,99.91 83.28,98.55 81.89,98.55 79.6,96.27 79.6,87.57 79.12,87.09 79.12,81.42 79.12,74.9 78.43,74.21 75.07,74.21 63.61,62.74 51.23,62.74 50.09,63.88 48.4,63.88 v1(47.88,64.4)
PRG0_RGMII2_TX_CTL_R: length 4
  TOP w0.173: U5.37 41.62,63.06 43.6,65.04 R59.2
PRG0_RGMII2_TXC: length 102.4
  TOP w0.173: R69.1 v1(46.74,56.4) ; J1.87 v1(84.01,119.01)
  L06_SIG2 w0.102: v1(46.74,56.4) 47.22,56.4 48.44,57.62 48.44,58.87 52.08,62.51 63.7,62.51 75.09,73.9 78.45,73.9 79.35,74.81 79.35,81.51 79.35,86.63 79.91,87.19 79.91,91.4 80.04,91.53 80.29,91.53 80.39,91.43 80.39,89.22 80.49,89.12 80.77,89.12 80.87,89.22 80.87,89.86 80.67,90.07 80.67,90.64 80.87,90.85 80.87,95.82 84.86,99.81 84.86,107.03 80.26,111.63 80.26,119.36 81.37,120.47 83.26,120.47 83.54,120.18 83.54,119.11 83.64,119.01 v1(84.01,119.01)
PRG0_RGMII2_TXC_R: length 3.1
  TOP w0.173: U5.29 42.44,57.62 43.76,57.62 R69.2
PRG0_RGMII2_XIN: length 2.3
  TOP w0.173: R73.2 37.12,53.17 U5.15
PRG0_RGMII2_XOUT: length 2.2
  TOP w0.173: R74.2 36.62,53.13 U5.14
PRG0_RGMII3_REF_CLK_R: length 1.9
  BOTTOM w0.173: U31.4 76.83,68.08 R208.1
PRG0_RGMII4_REF_CLK_R: length 2.1
  BOTTOM w0.173: U31.5 68.13,68.08 R207.1
PRG0_RGMII_INT#: length 75.7
  TOP w0.173: R86.1 52.99,40.33 53.16,40.5 v1(53.74,40.5) 54.48,39.77 58.97,39.77 61.51,37.23 73.51,37.23 82.4,46.12 83.17,46.12 83.67,46.63 J2.15 ; U5.44 38.12,62.72 v1(38.05,62.79)
  L03_SIG1 w0.102: v1(53.74,40.5) 53.74,42.79 51.38,45.15 41,45.15 36.5,49.65 36.5,61.23 v1(38.05,62.79)
  BOTTOM w0.173: U37.44 v1(53.74,40.5)
PRG1_IEP0_EDIO_OUTVALID: length 83.9
  TOP w0.173: J2.26 93.08,49.13 v1(93.58,49.63)
  L03_SIG1 w0.102: v1(93.58,49.63) 93.58,33.82 92.28,32.53 92.28,20.28 90.14,18.15 51.74,18.15 50.65,17.05 47.17,17.05 46.52,17.7 45.07,17.7 43.91,16.54 J24.41
PRG1_MDC: length 59.9
  TOP w0.173: v1(59.37,58.45) 58.85,58.96 58.85,59.94 58.4,60.39 53.24,60.39 52.05,61.58 52.05,65.15 48.84,68.36 48.84,79.21 50.44,80.81 55.66,80.81 v1(56.16,80.3) ; U3.16 v1(37.62,84.7)
  L03_SIG1 w0.102: v1(56.16,80.3) 55.5,80.96 46.33,80.96 43.18,84.11 38.21,84.11 v1(37.62,84.7)
  BOTTOM w0.173: U35.9 v1(59.37,58.45) ; U30.16 v1(56.16,80.3)
PRG1_MDIO: length 61.7
  TOP w0.173: U3.17 38.12,85.16 38.51,84.77 38.51,84.72 38.51,84.72 v1(38.51,84.7) ; v1(57.05,80.3) 56.19,81.17 49.99,81.17 48.5,79.68 48.5,68.2 51.69,65.01 51.69,61.2 53.15,59.75 v1(58.35,59.75)
  L03_SIG1 w0.102: v1(38.51,84.7) 43,84.7 46.33,81.37 55.99,81.37 v1(57.05,80.3)
  BOTTOM w0.173: U35.12 59,60.4 v1(58.35,59.75) ; v1(57.05,80.3) 57.05,80.28 57.05,80.28 57.05,80.23 56.66,79.84 U30.17
PRG1_MDIO0_MDC: length 6.7
  BOTTOM w0.173: U35.2 64.85,62.35 62.25,59.75 U35.11
PRG1_MDIO0_MDIO: length 19.3
  TOP w0.173: R288.1 74.88,61.45 73.36,59.93 68.27,59.93 v1(67.8,60.4) 67.24,60.4 65.94,61.7 v1(62.04,61.7)
  BOTTOM w0.173: U35.14 v1(62.04,61.7) ; U35.5 v1(67.8,60.4)
PRG1_PRU0_GPO10: length 45.6
  TOP w0.173: v1(93.58,99.01) 93.08,99.51 J1.30
  L03_SIG1 w0.102: v1(93.58,99.01) 93.09,99.49 93.09,99.83 92.37,100.55 88.38,100.55 86.34,102.58 86.34,103.75 84.59,105.5 70.51,105.5 64.49,111.52 64.49,117.56 v1(64.01,118.04)
  BOTTOM w0.173: U23.4 v1(64.01,118.04)
PRG1_PRU1_GPO5: length 121.2
  L06_SIG2 w0.102: v1(68.09,94) 67.86,93.77 57.35,93.77 52.27,88.69 52.27,74.57 44.91,67.2 44.91,57.88 44.04,57.02 44.04,52.12 42.77,50.85 42.77,32.27 55.58,19.47 74.52,19.47 75.91,18.09 J24.9
  BOTTOM w0.173: U29.42 v1(68.09,94)
PRG1_PRU1_GPO9: length 52.8
  TOP w0.173: v1(82.86,99.01) 83.36,99.51 J1.29
  L06_SIG2 w0.102: v1(82.86,99.01) 83.56,99.7 83.56,100.67 82.3,101.92 82.29,101.92 82.02,102.19 82.02,102.21 81.22,103 81.22,105.01 82.83,106.62 82.83,107.76 82.59,107.99 81.88,107.99 77.02,112.86 77.02,121.44 73.77,124.69 68.31,124.69 65.77,122.15 65.77,116.18 v1(65.02,115.44)
  BOTTOM w0.173: v1(65.02,115.44) 64.37,116.09 U23.7
PRG1_PRU1_GPO10: length 39.4
  TOP w0.173: J1.31 83.07,100.01 81.75,98.69 79.92,98.69 v1(79.87,98.74)
  BOTTOM w0.173: U23.9 58.56,115.44 61.84,112.17 61.84,109.9 67.25,104.49 78.62,104.49 79.87,103.24 v1(79.87,98.74)
PRG1_PWM0_A0: length 151
  L06_SIG2 w0.102: v1(74.86,113.98) 74.99,113.85 74.99,107.06 73.98,106.05 73.98,85.25 66.98,78.25 66.98,77.08 65.84,75.94 65.84,75.45 64.21,73.82 64.21,67.95 61.1,64.84 51.45,64.84 51.1,65.18 50.32,65.97 46.15,65.97 45.64,65.46 45.64,56.81 45.19,56.36 45.19,45.67 44.78,45.26 44.78,40.58 44.78,35.68 60.22,20.23 79.32,20.23 80.91,18.65 80.91,14.48 J24.4
  BOTTOM w0.173: v1(74.86,113.98) 74.97,114.09 R357.2
PRG1_PWM0_A1: length 147.7
  L06_SIG2 w0.102: J24.6 78.91,14.48 78.91,18.34 77.27,19.98 59.99,19.98 44.32,35.65 44.32,40.77 44.32,40.77 44.32,48.5 44.16,48.67 44.16,51.26 44.73,51.83 44.73,56.55 45.39,57.21 45.39,65.8 45.79,66.2 50.45,66.2 51.49,65.17 61.03,65.17 63.83,67.97 63.83,75.32 64.78,76.27 65.56,76.27 66.52,77.22 66.52,78.43 73.75,85.67 73.75,106.14 74.6,106.99 74.6,110.85 74.43,111.02 74.4,111.02 v1(74.39,111.03)
  BOTTOM w0.173: R359.2 74.58,111.21 v1(74.39,111.03)
PRG1_PWM0_A2: length 143.7
  L06_SIG2 w0.102: J24.8 76.91,14.48 76.91,18.48 75.67,19.73 59.8,19.73 43.87,35.66 43.87,45.64 43.87,48.31 43.7,48.48 43.7,51.45 44.27,52.02 44.27,56.88 45.14,57.74 45.14,66 45.62,66.49 50.57,66.49 51.56,65.5 60.95,65.5 63.37,67.92 63.37,76 64.78,77.41 65.53,77.41 66.06,77.94 66.06,78.65 72.03,84.63 72.03,106.34 73.65,107.95 v1(74.07,107.95)
  BOTTOM w0.173: v1(74.07,107.95) 74.35,108.24 R361.2
PRG1_PWM0_B0: length 29.4
  TOP w0.173: U41.11 v1(60.21,133.92)
  L03_SIG1 w0.102: v1(72.68,112.39) 71.85,112.39 68.71,115.53 68.71,125.42 v1(60.21,133.92)
  BOTTOM w0.173: v1(72.68,112.39) 72.74,112.44 R358.2
PRG1_PWM0_B1: length 32.8
  TOP w0.173: U41.13 v1(59.21,133.92)
  L03_SIG1 w0.102: v1(72.83,109.46) 71.7,109.46 67.66,113.5 67.66,125.47 v1(59.21,133.92)
  BOTTOM w0.173: v1(72.83,109.46) 72.89,109.51 R360.2
PRG1_PWM0_B2: length 49.4
  TOP w0.173: U41.21 55.21,134.01 56.62,132.6 62.66,132.6 68.76,126.51 68.76,101.74 67.21,100.19 67.21,97.88 v1(68.09,97)
  BOTTOM w0.173: U29.48 v1(68.09,97)
PRG1_PWM0_TZ_IN: length 121.5
  L06_SIG2 w0.102: v1(68.09,96) 67.64,95.54 57.66,95.54 51.66,89.55 51.66,76.55 44.45,69.34 44.45,60.78 42.32,58.64 42.32,32.01 55.39,18.94 72.85,18.94 73.91,17.88 J24.11
  BOTTOM w0.173: U29.46 v1(68.09,96)
PRG1_PWM0_TZ_OUT: length 124.2
  L06_SIG2 w0.102: J24.10 75.9,13.48 74.91,14.46 74.91,17.97 73.66,19.22 55.47,19.22 42.55,32.15 42.55,50.94 43.81,52.21 43.81,57.11 44.68,57.98 44.68,67.3 51.92,74.54 51.92,89.4 57.76,95.24 67.85,95.24 v1(68.09,95)
  BOTTOM w0.173: U29.44 v1(68.09,95)
PRG1_PWM2_A0: length 19.6
  TOP w0.173: U41.6 v1(62.71,133.92)
  L03_SIG1 w0.102: v1(72.82,120.78) 72.15,120.78 69.62,123.31 69.62,127.01 v1(62.71,133.92)
  BOTTOM w0.173: v1(72.82,120.78) 72.84,120.75 R352.2
PRG1_PWM2_A1: length 46.8
  TOP w0.173: v1(68.09,98.5) 67.59,99 67.59,99.81 69.14,101.36 69.14,126.79 62.97,132.96 57.71,132.96 56.71,133.96 U41.18
  BOTTOM w0.173: U29.51 v1(68.09,98.5)
PRG1_PWM2_B0: length 136.1
  L06_SIG2 w0.102: J24.19 65.91,15.48 65.91,16.48 64.22,18.18 54.92,18.18 40.08,33.02 40.08,50.24 39.18,51.14 39.18,52.89 41.25,54.96 41.25,59.52 43.76,62.03 43.76,71.88 50.77,78.88 50.77,90.07 56.52,95.82 56.52,104.18 65.52,113.19 65.52,114.88 68.5,117.86 v1(72.36,117.86)
  BOTTOM w0.173: R354.2 v1(72.36,117.86)
PRG1_PWM2_B1: length 226.3
  L06_SIG2 w0.102: J24.29 55.91,16.47 55.55,16.83 53.79,16.83 36.41,34.21 36.41,57.11 39.44,60.14 39.44,60.7 40.84,62.11 40.84,72.27 50,81.42 50,93.42 55.73,99.15 55.73,109.11 64.06,117.44 64.42,117.44 v1(65.02,118.04)
  BOTTOM w0.173: J5.7 68.51,184.51 68.99,184.04 68.99,178.02 46.22,155.25 46.22,143.04 48.99,140.27 68.25,140.27 69,139.52 69,122.02 v1(65.02,118.04) 64.37,118.69 U23.3
PRG1_PWM3_A0: length 16.3
  TOP w0.173: U41.2 v1(64.71,133.92)
  L03_SIG1 w0.102: v1(64.71,133.92) 64.99,133.92 72.44,126.47 v1(72.44,123.24)
  BOTTOM w0.173: v1(72.44,123.24) 72.47,123.27 R350.2
PRG1_PWM3_A1: length 138.8
  L06_SIG2 w0.102: J24.17 67.91,16.44 65.92,18.43 54.99,18.43 40.46,32.96 40.46,50.15 40.47,50.16 40.47,51.16 40.16,51.47 40.16,53.46 41.48,54.78 41.48,59.42 43.99,61.94 43.99,71.79 50.99,78.79 50.99,89.82 57.07,95.9 57.07,102.94 66.29,112.15 66.29,114.32 69,117.04 73.14,117.04 v1(73.16,117.06)
  BOTTOM w0.173: R355.2 75.43,116.18 74.72,116.18 73.85,117.06 v1(73.16,117.06)
PRG1_PWM3_A2: length 23.9
  TOP w0.173: U41.9 v1(61.21,133.92)
  L03_SIG1 w0.102: v1(61.21,133.92) 69.29,125.84 69.29,122.55 72.68,119.16 74.53,119.16 v1(74.55,119.13)
  BOTTOM w0.173: v1(74.55,119.13) 74.67,119.26 R353.2
PRG1_PWM3_B0: length 20
  TOP w0.173: U41.4 v1(63.71,133.92)
  L03_SIG1 w0.102: v1(63.71,133.92) 69.93,127.7 69.93,124.81 72.8,121.94 v1(74.79,121.94)
  BOTTOM w0.173: R351.2 74.86,122.01 v1(74.79,121.94)
PRG1_PWM3_B1: length 44.5
  TOP w0.173: U41.15 58.21,134.11 58.98,133.34 63.25,133.34 69.49,127.09 69.49,100.9 v1(68.09,99.5)
  BOTTOM w0.173: U29.53 v1(68.09,99.5)
PRG1_PWM3_B2: length 63.6
  TOP w0.173: J2.27 v1(84,49.63)
  L06_SIG2 w0.102: v1(48.92,18.87) 48.91,18.86 48.91,14.48 J24.38
  BOTTOM w0.173: v1(84,49.63) 84,48.35 84.58,47.77 84.58,41.67 82.35,39.44 75.87,39.44 70.03,33.59 57.96,33.59 48.92,24.55 v1(48.92,18.87)
PRG1_PWM3_TZ_OUT: length 135.8
  L06_SIG2 w0.102: J24.15 66.7,18.68 55.06,18.68 40.69,33.06 40.69,50.05 41.08,50.44 41.08,53.62 41.71,54.24 41.71,59.33 44.22,61.84 44.22,71.69 51.22,78.69 51.22,89.59 57.38,95.75 57.38,102.5 66.67,111.79 66.67,113.73 68.49,115.54 72.48,115.54 v1(72.72,115.31)
  BOTTOM w0.173: R356.2 v1(72.72,115.31)
PRG1_RGMII1_100MBPS: length 15.6
  TOP w0.173: Q3.3 6.86,67.05 R48.2 7.09,67.32 4.22,70.2 4.22,74.92 5,75.7 J20.A13
PRG1_RGMII1_1000MBPS: length 10.1
  TOP w0.173: J20.A14 14.24,68.43 R50.2 13.97,67.05 Q5.3
PRG1_RGMII1_ACT_LED: length 8.7
  TOP w0.173: J20.A11 11.18,81.94 Q1.3
PRG1_RGMII1_CLK_OUT: length 7.7
  TOP w0.173: v1(57.16,78.49) 56.14,79.52 v1(53.7,79.52)
  BOTTOM w0.173: v1(53.7,79.52) 53.21,79.52 TP12.1 ; U30.18 v1(57.16,78.49)
PRG1_RGMII1_D0_N: length 45.1
  BOTTOM w0.102: J20.A2 13.87,74.59 13.87,73.57 14.15,73.29 14.15,71.21 14.98,70.38 45.86,70.38 48.94,73.46 53.14,73.46 53.26,73.58 U30.2
PRG1_RGMII1_D0_P: length 45.1
  BOTTOM w0.102: U30.1 53.26,73.08 53.14,73.19 49.05,73.19 45.97,70.11 14.87,70.11 13.88,71.1 13.88,73.18 13.64,73.42 J20.A1
PRG1_RGMII1_D1_N: length 42.6
  BOTTOM w0.102: J20.A4 16.41,74.59 16.41,73.57 16.69,73.29 16.69,71.19 16.79,71.09 43.26,71.09 47.13,74.96 53.14,74.96 53.26,75.08 U30.5
PRG1_RGMII1_D1_P: length 42.6
  BOTTOM w0.102: U30.4 53.26,74.58 53.14,74.69 47.24,74.69 43.37,70.82 16.68,70.82 16.42,71.08 16.42,73.18 16.18,73.42 J20.A3
PRG1_RGMII1_D2_N: length 39.6
  BOTTOM w0.102: J20.A6 18.92,74.56 18.92,73.62 19.23,73.32 19.23,72.08 19.56,71.75 40.62,71.75 45.33,76.46 53.14,76.46 53.26,76.58 U30.8
PRG1_RGMII1_D2_P: length 39.7
  BOTTOM w0.102: J20.A5 18.75,73.42 18.96,73.21 18.96,71.97 19.45,71.48 40.73,71.48 45.44,76.19 53.14,76.19 53.26,76.08 U30.7
PRG1_RGMII1_D3_N: length 36.9
  BOTTOM w0.102: J20.A8 21.49,74.59 21.49,73.57 21.77,73.29 21.77,72.48 21.89,72.36 39.45,72.36 45.05,77.96 53.14,77.96 53.26,78.08 U30.11
PRG1_RGMII1_D3_P: length 37
  BOTTOM w0.102: J20.A7 21.26,73.42 21.5,73.18 21.5,72.36 21.78,72.09 39.56,72.09 45.16,77.69 53.14,77.69 53.26,77.58 U30.10
PRG1_RGMII1_GPIO0_100: length 71.5
  TOP w0.173: v1(58.42,69.92) R46.1 ; Q3.1 v1(5.91,64.42)
  L03_SIG1 w0.102: v1(58.42,69.92) 57.58,69.08 55.02,69.08 53.67,67.73 53.67,65.45 51.6,63.38 51.6,61.62 48.51,58.53 44.84,58.53 41.91,61.46 41.91,64.36 41.38,64.89 32.61,64.89 29.45,61.72 8.58,61.72 5.91,64.39 v1(5.91,64.42)
  BOTTOM w0.173: R46.1 v1(58.42,69.92) 59.32,70.81 59.32,71.71 59.25,71.79 59.25,71.83 59.16,71.91 U30.39
PRG1_RGMII1_GPIO1: length 4.9
  TOP w0.173: v1(57.28,69.92) R45.1
  BOTTOM w0.173: U30.40 58.66,71.92 58.75,71.84 58.75,71.79 58.97,71.56 58.97,71.21 58.68,70.92 58.66,70.92 57.66,69.92 v1(57.28,69.92) R45.1
PRG1_RGMII1_LED0: length 4.4
  TOP w0.173: v1(53.85,69.92) R42.1
  BOTTOM w0.173: R42.1 v1(53.85,69.92) 55.16,71.23 U30.47
PRG1_RGMII1_LED1_1000: length 60.3
  TOP w0.173: v1(54.99,69.92) R43.1 ; Q5.1 v1(13.02,64.42)
  L03_SIG1 w0.102: v1(13.02,64.42) 13.06,64.42 15.31,62.18 29.2,62.18 32.37,65.34 41.57,65.34 42.52,64.4 42.52,62.75 46.29,58.99 48,58.99 50.99,61.97 50.99,63.61 52.53,65.15 52.53,68.47 53.49,69.43 54.51,69.43 v1(54.99,69.92)
  BOTTOM w0.173: U30.46 55.66,70.59 v1(54.99,69.92) R43.1
PRG1_RGMII1_LED2_ACT: length 98.2
  TOP w0.173: v1(56.13,69.92) R44.1 ; Q1.1 v1(12.13,90.73)
  L03_SIG1 w0.102: v1(56.13,69.92) 55.52,69.31 54.92,69.31 53.44,67.83 53.44,65.67 51.23,63.46 51.23,61.84 48.15,58.76 46.13,58.76 42.29,62.6 42.29,64.3 41.48,65.12 32.46,65.12 29.3,61.95 9.44,61.95 5.71,65.67 5.71,87.82 7.32,89.42 10.82,89.42 v1(12.13,90.73)
  BOTTOM w0.173: U30.45 56.13,72.3 v1(56.13,69.92) R44.1
PRG1_RGMII1_RBIAS: length 2.3
  TOP w0.173: v1(52.83,78.58) 53.88,78.58 R36.2
  BOTTOM w0.173: U30.12 v1(52.83,78.58)
PRG1_RGMII1_RD0: length 64.9
  L06_SIG2 w0.102: v1(68.19,73.09) 67.8,72.69 67.8,72.27 68.45,71.61 69.55,71.61 69.97,72.04 69.97,74.1 68.98,75.09 68.98,78.1 76.73,85.85 76.73,121.34 73.91,124.17 71.71,124.17 v1(71.69,124.15)
  BOTTOM w0.173: R192.1 v1(68.19,73.09) ; v1(71.69,124.15) 71.69,124.17 71.78,124.25 R338.2
PRG1_RGMII1_RD0_R: length 6.9
  BOTTOM w0.173: 63.5,72.86 R38.2 ; 63.5,72.86 R37.1 62.08,74.06 61.62,74.51 60.98,74.51 U30.33 ; 63.5,72.86 64.07,73.42 64.9,73.42 65.24,73.09 R192.2
PRG1_RGMII1_RD1: length 64.2
  L06_SIG2 w0.102: v1(74.3,122.83) 74.3,123.29 73.83,123.76 73.11,123.76 72.92,123.58 72.92,122.65 73.14,122.43 75.28,122.43 76.5,121.2 76.5,85.99 68.53,78.02 68.53,74.37 67.61,73.45 66.5,73.45 66.04,72.99 66.04,72.36 v1(66.22,72.18)
  BOTTOM w0.173: R193.1 65.2,71.7 65.34,71.57 65.84,71.57 66.22,71.95 v1(66.22,72.18) ; R339.2 74.46,122.99 v1(74.3,122.83)
PRG1_RGMII1_RD1_R: length 4.2
  BOTTOM w0.173: U30.34 61.44,74.08 62.55,72.97 62.55,71.92 62.77,71.7 R193.2
PRG1_RGMII1_RD2: length 64.4
  L06_SIG2 w0.102: v1(71.75,121.88) 71.39,121.88 71.21,122.05 71.21,122.43 71.42,122.63 72.37,122.63 73.12,121.88 74.13,121.88 76.12,119.88 76.12,85.94 68.16,77.97 68.16,76.02 64.9,72.77 64.9,71.91 65.8,71.01 v1(66.42,71.01)
  BOTTOM w0.173: v1(71.75,121.88) 71.9,121.73 R340.2 ; v1(66.42,71.01) 66.42,70.93 66.96,70.4 R195.1
PRG1_RGMII1_RD2_R: length 9.2
  BOTTOM w0.173: U30.35 61.41,73.58 62.06,72.93 62.06,71.35 62.85,70.56 R39.2 R40.1 63.48,69.01 63.73,68.77 65.34,68.77 R195.2
PRG1_RGMII1_RD3: length 64.3
  L06_SIG2 w0.102: v1(65.56,68.17) 65.9,68.51 65.9,70.37 64.67,71.6 64.67,72.86 67.93,76.12 67.93,78.06 75.16,85.3 75.16,92.69 75.8,93.33 75.81,93.33 75.9,93.42 75.9,119.49 73.88,121.51 73.51,121.51 73.27,121.27 73.27,120.26 73.64,119.89 74.03,119.89 v1(74.23,120.1)
  BOTTOM w0.173: v1(65.56,68.17) 65.45,68.06 R197.1 ; v1(74.23,120.1) 74.37,120.24 R341.2
